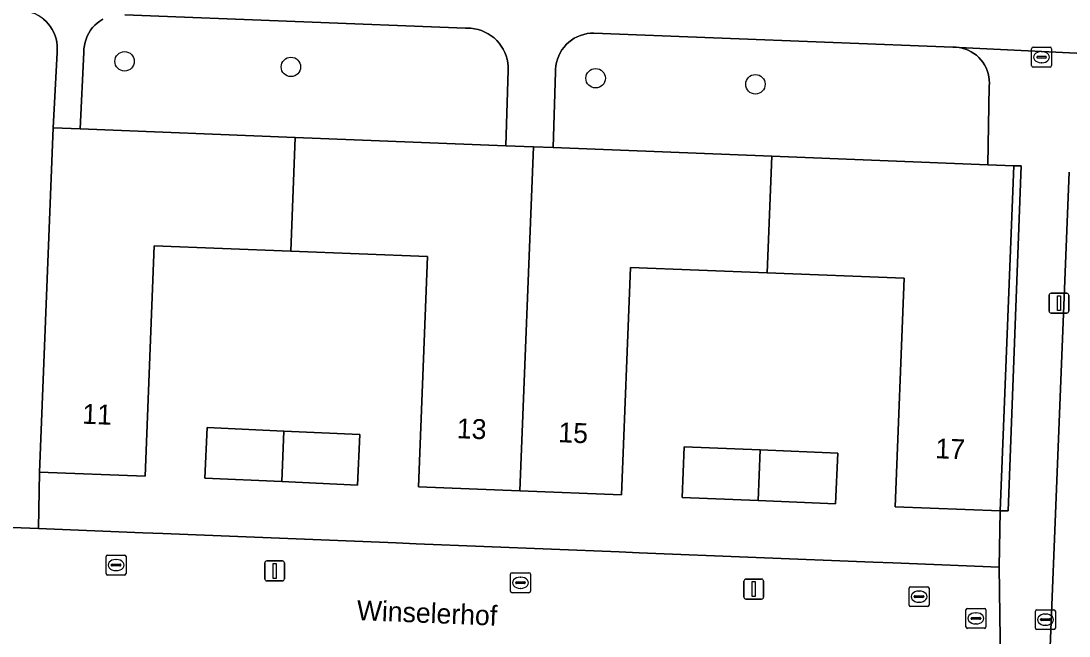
# Model space of a CAD drawing. Extents: x 160786 to 161429, y 386828 to 387485.
# Drawn here: x 161039.4 to 161092.1, y 387016.5 to 387047.4 of the extents above; entities that cross this region are included whole.
import ezdxf

# ---------------------------------------------------------------- set-up
doc = ezdxf.new("R2010")
doc.units = 0
for name, color, linetype in [('IMGEO_Boom', 7, 'Continuous'), ('IMGEO_Brandkraan', 7, 'Continuous'), ('IMGEO_Erf', 7, 'Continuous'), ('IMGEO_Grasland_overig', 7, 'Continuous'), ('IMGEO_Groenvoorziening', 7, 'Continuous'), ('IMGEO_Kolk', 7, 'Continuous'), ('IMGEO_Lichtmast', 7, 'Continuous'), ('IMGEO_Openbare_ruimte_label', 7, 'Continuous'), ('IMGEO_Pand', 7, 'Continuous'), ('IMGEO_Pand_nummerreeks', 7, 'Continuous'), ('IMGEO_Rioolput', 7, 'Continuous'), ('IMGEO_Voetpad_open', 7, 'Continuous')]:
    doc.layers.add(name, color=color, linetype=linetype)

msp = doc.modelspace()

# ---------------------------------------------------------------- linework, layer by layer
at = {"layer": 'IMGEO_Boom'}
for centre in [(161044.621, 387045.348), (161052.986, 387045.068), (161068.308, 387044.499), (161076.343, 387044.195)]:
    msp.add_circle(centre, 0.489, dxfattribs=at)
at = {"layer": 'IMGEO_Brandkraan'}
for p, q in [((161090.233, 387045.132), (161090.233, 387045.984)), ((161090.308, 387046.058), (161091.16, 387046.058)), ((161090.492, 387045.552), (161090.492, 387045.564)), ((161090.535, 387045.601), (161090.933, 387045.601)), ((161090.721, 387045.838), (161090.746, 387045.838)), ((161090.976, 387045.564), (161090.976, 387045.552)), ((161091.234, 387045.984), (161091.234, 387045.132)), ((161091.16, 387045.058), (161090.308, 387045.058)), ((161090.93, 387045.515), (161090.532, 387045.515)), ((161090.744, 387045.278), (161090.719, 387045.278))]:
    msp.add_line(p, q, dxfattribs=at)
for points in [[(161090.233, 387045.132), (161090.233, 387045.984)], [(161090.308, 387046.058), (161091.16, 387046.058)], [(161091.234, 387045.984), (161091.234, 387045.132)], [(161091.16, 387045.058), (161090.308, 387045.058)]]:
    msp.add_lwpolyline(points, dxfattribs=at)
for centre, radius, start, end in [((161090.31, 387045.982), 0.0765, 91.552, 178.448), ((161090.31, 387045.982), 0.0765, 91.552, 178.448), ((161090.532, 387045.561), 0.0403, 85.8775, 175.7526), ((161090.529, 387045.551), 0.0366, 178.938, 274.7102), ((161090.933, 387045.558), 0.043, 264.8664, 352.4533), ((161090.937, 387045.563), 0.0386, 1.7309, 96.639), ((161091.158, 387045.982), 0.0765, 1.552, 88.448), ((161091.158, 387045.982), 0.0765, 1.552, 88.448), ((161090.31, 387045.134), 0.0765, 181.552, 268.448), ((161090.31, 387045.134), 0.0765, 181.552, 268.448), ((161091.158, 387045.134), 0.0765, 271.552, 358.448), ((161091.158, 387045.134), 0.0765, 271.552, 358.448)]:
    msp.add_arc(centre, radius, start, end, dxfattribs=at)
for centre, major_axis, ratio, start_param, end_param in [((161090.72, 387045.558), (-0.387, 0.002), 0.722429, 4.712389, 7.853982), ((161090.745, 387045.558), (-0.39, 0.002), 0.717154, 1.570796, 4.712389)]:
    msp.add_ellipse(centre, major_axis=major_axis, ratio=ratio, start_param=start_param, end_param=end_param, dxfattribs=at)
at = {"layer": 'IMGEO_Erf'}
msp.add_lwpolyline([(161092.128, 387039.776), (161090.524, 387000), (161090.045, 386988.116), (161088.04, 386938.415)], dxfattribs=at)
for points in [[(161088.653, 387022.747), (161083.368, 387022.956), (161083.821, 387034.446), (161076.938, 387034.717), (161070.057, 387034.988), (161069.606, 387023.557), (161064.5, 387023.758), (161059.398, 387023.959), (161059.855, 387035.539), (161052.982, 387035.81), (161046.111, 387036.081), (161045.654, 387024.488), (161040.347, 387024.697), (161040.297, 387021.856), (161045.542, 387021.645), (161046.541, 387021.605), (161058.286, 387021.134), (161059.285, 387021.094), (161069.492, 387020.685), (161070.491, 387020.645), (161082.258, 387020.173), (161083.257, 387020.133), (161088.605, 387019.918)], [(161056.335, 387024.044), (161052.525, 387024.218), (161048.651, 387024.394), (161048.767, 387026.938), (161052.626, 387026.762), (161056.451, 387026.588)], [(161076.487, 387023.268), (161072.653, 387023.428), (161072.759, 387025.972), (161076.587, 387025.812), (161080.481, 387025.65), (161080.375, 387023.106)]]:
    msp.add_lwpolyline(points, close=True, dxfattribs=at)
at = {"layer": 'IMGEO_Grasland_overig'}
msp.add_lwpolyline([(161088.036, 387040.148), (161088.101, 387044.096), (161088.11, 387044.255), (161088.104, 387044.415), (161088.085, 387044.573), (161088.051, 387044.729), (161088.003, 387044.882), (161087.942, 387045.029), (161087.869, 387045.171), (161087.782, 387045.305), (161087.684, 387045.431), (161087.576, 387045.548), (161087.457, 387045.655), (161087.329, 387045.75), (161087.193, 387045.834), (161087.05, 387045.906), (161086.902, 387045.964), (161086.748, 387046.009), (161086.592, 387046.04), (161086.433, 387046.056), (161086.278, 387046.059), (161068.217, 387046.773), (161068.046, 387046.766), (161067.875, 387046.743), (161067.708, 387046.706), (161067.545, 387046.653), (161067.387, 387046.586), (161067.235, 387046.506), (161067.091, 387046.412), (161066.957, 387046.306), (161066.832, 387046.188), (161066.718, 387046.059), (161066.617, 387045.921), (161066.528, 387045.774), (161066.452, 387045.62), (161066.391, 387045.46), (161066.344, 387045.295), (161066.312, 387045.126), (161066.295, 387044.955), (161066.293, 387044.826), (161066.166, 387041.01), (161077.169, 387040.577)], close=True, dxfattribs=at)
at = {"layer": 'IMGEO_Groenvoorziening'}
for points in [[(161035.04, 387022.067), (161040.297, 387021.856), (161040.347, 387024.697), (161041.029, 387042.001), (161041.225, 387045.801), (161041.235, 387045.97), (161041.23, 387046.14), (161041.21, 387046.309), (161041.175, 387046.475), (161041.126, 387046.637), (161041.062, 387046.794), (161040.984, 387046.945), (161040.893, 387047.088), (161040.789, 387047.223), (161040.674, 387047.348), (161040.549, 387047.462), (161040.413, 387047.564), (161040.269, 387047.654), (161040.118, 387047.731), (161039.96, 387047.793), (161039.797, 387047.842), (161039.631, 387047.876), (161039.462, 387047.894), (161039.293, 387047.898)], [(161043.519, 387047.463), (161043.378, 387047.375), (161043.245, 387047.275), (161043.123, 387047.164), (161043.01, 387047.042), (161042.909, 387046.91), (161042.82, 387046.77), (161042.744, 387046.622), (161042.681, 387046.469), (161042.633, 387046.31), (161042.598, 387046.148), (161042.579, 387045.983), (161042.574, 387045.815), (161042.387, 387041.947), (161053.207, 387041.521), (161063.786, 387041.104), (161063.914, 387044.91), (161063.912, 387045.093), (161063.893, 387045.274), (161063.858, 387045.453), (161063.808, 387045.629), (161063.742, 387045.799), (161063.661, 387045.963), (161063.565, 387046.118), (161063.456, 387046.265), (161063.335, 387046.401), (161063.202, 387046.526), (161063.058, 387046.638), (161062.905, 387046.738), (161062.743, 387046.823), (161062.575, 387046.893), (161062.4, 387046.948), (161062.222, 387046.987), (161062.041, 387047.01), (161061.859, 387047.017), (161061.76, 387047.014), (161044.639, 387047.69)]]:
    msp.add_lwpolyline(points, dxfattribs=at)
msp.add_lwpolyline([(161088.653, 387022.747), (161089.055, 387022.743), (161089.703, 387040.094), (161089.337, 387040.097)], close=True, dxfattribs=at)
at = {"layer": 'IMGEO_Kolk'}
for p, q in [((161043.693, 387019.597), (161043.693, 387020.449)), ((161043.768, 387020.523), (161044.62, 387020.523)), ((161044.181, 387020.303), (161044.206, 387020.303)), ((161044.694, 387020.449), (161044.694, 387019.597)), ((161043.952, 387020.017), (161043.952, 387020.029)), ((161044.39, 387019.98), (161043.992, 387019.98)), ((161043.995, 387020.066), (161044.393, 387020.066)), ((161044.204, 387019.743), (161044.179, 387019.743)), ((161044.436, 387020.029), (161044.436, 387020.017)), ((161044.62, 387019.523), (161043.768, 387019.523)), ((161064.029, 387018.708), (161064.029, 387019.56)), ((161064.104, 387019.634), (161064.956, 387019.634)), ((161064.517, 387019.414), (161064.542, 387019.414)), ((161065.03, 387019.56), (161065.03, 387018.708)), ((161064.288, 387019.128), (161064.288, 387019.14)), ((161064.726, 387019.091), (161064.328, 387019.091)), ((161064.331, 387019.177), (161064.729, 387019.177)), ((161064.54, 387018.854), (161064.515, 387018.854)), ((161064.772, 387019.14), (161064.772, 387019.128)), ((161084.072, 387018.01), (161084.072, 387018.862)), ((161084.147, 387018.936), (161084.999, 387018.936)), ((161084.56, 387018.716), (161084.585, 387018.716)), ((161085.073, 387018.862), (161085.073, 387018.01)), ((161064.956, 387018.634), (161064.104, 387018.634)), ((161084.331, 387018.43), (161084.331, 387018.442)), ((161084.769, 387018.393), (161084.371, 387018.393)), ((161084.374, 387018.479), (161084.772, 387018.479)), ((161084.583, 387018.156), (161084.558, 387018.156)), ((161084.815, 387018.442), (161084.815, 387018.43)), ((161084.999, 387017.936), (161084.147, 387017.936))]:
    msp.add_line(p, q, dxfattribs=at)
for points in [[(161043.693, 387019.597), (161043.693, 387020.449)], [(161043.768, 387020.523), (161044.62, 387020.523)], [(161044.694, 387020.449), (161044.694, 387019.597)], [(161044.62, 387019.523), (161043.768, 387019.523)], [(161064.029, 387018.708), (161064.029, 387019.56)], [(161064.104, 387019.634), (161064.956, 387019.634)], [(161065.03, 387019.56), (161065.03, 387018.708)], [(161084.072, 387018.01), (161084.072, 387018.862)], [(161084.147, 387018.936), (161084.999, 387018.936)], [(161085.073, 387018.862), (161085.073, 387018.01)], [(161064.956, 387018.634), (161064.104, 387018.634)], [(161084.999, 387017.936), (161084.147, 387017.936)]]:
    msp.add_lwpolyline(points, dxfattribs=at)
for centre, radius, start, end in [((161043.77, 387020.447), 0.0765, 91.552, 178.448), ((161043.77, 387020.447), 0.0765, 91.552, 178.448), ((161044.618, 387020.447), 0.0765, 1.552, 88.448), ((161044.618, 387020.447), 0.0765, 1.552, 88.448), ((161043.992, 387020.026), 0.0403, 85.8775, 175.7526), ((161043.989, 387020.016), 0.0366, 178.938, 274.7102), ((161044.393, 387020.023), 0.043, 264.8664, 352.4533), ((161044.397, 387020.028), 0.0386, 1.7309, 96.639), ((161043.77, 387019.599), 0.0765, 181.552, 268.448), ((161043.77, 387019.599), 0.0765, 181.552, 268.448), ((161044.618, 387019.599), 0.0765, 271.552, 358.448), ((161044.618, 387019.599), 0.0765, 271.552, 358.448), ((161064.106, 387019.558), 0.0765, 91.552, 178.448), ((161064.106, 387019.558), 0.0765, 91.552, 178.448), ((161064.954, 387019.558), 0.0765, 1.552, 88.448), ((161064.954, 387019.558), 0.0765, 1.552, 88.448), ((161064.106, 387018.71), 0.0765, 181.552, 268.448), ((161064.106, 387018.71), 0.0765, 181.552, 268.448), ((161064.328, 387019.137), 0.0403, 85.8775, 175.7526), ((161064.325, 387019.127), 0.0366, 178.938, 274.7102), ((161064.729, 387019.134), 0.043, 264.8664, 352.4533), ((161064.733, 387019.139), 0.0386, 1.7309, 96.639), ((161064.954, 387018.71), 0.0765, 271.552, 358.448), ((161064.954, 387018.71), 0.0765, 271.552, 358.448), ((161084.149, 387018.86), 0.0765, 91.552, 178.448), ((161084.149, 387018.86), 0.0765, 91.552, 178.448), ((161084.997, 387018.86), 0.0765, 1.552, 88.448), ((161084.997, 387018.86), 0.0765, 1.552, 88.448), ((161084.371, 387018.439), 0.0403, 85.8775, 175.7526), ((161084.368, 387018.429), 0.0366, 178.938, 274.7102), ((161084.772, 387018.436), 0.043, 264.8664, 352.4533), ((161084.776, 387018.441), 0.0386, 1.7309, 96.639), ((161084.149, 387018.012), 0.0765, 181.552, 268.448), ((161084.149, 387018.012), 0.0765, 181.552, 268.448), ((161084.997, 387018.012), 0.0765, 271.552, 358.448), ((161084.997, 387018.012), 0.0765, 271.552, 358.448)]:
    msp.add_arc(centre, radius, start, end, dxfattribs=at)
for centre, major_axis, ratio, start_param, end_param in [((161044.18, 387020.023), (-0.387, 0.002), 0.722429, 4.712389, 7.853982), ((161044.205, 387020.023), (-0.39, 0.002), 0.717154, 1.570796, 4.712389), ((161064.516, 387019.134), (-0.387, 0.002), 0.722429, 4.712389, 7.853982), ((161064.541, 387019.134), (-0.39, 0.002), 0.717154, 1.570796, 4.712389), ((161084.559, 387018.436), (-0.387, 0.002), 0.722429, 4.712389, 7.853982), ((161084.584, 387018.436), (-0.39, 0.002), 0.717154, 1.570796, 4.712389)]:
    msp.add_ellipse(centre, major_axis=major_axis, ratio=ratio, start_param=start_param, end_param=end_param, dxfattribs=at)
at = {"layer": 'IMGEO_Lichtmast'}
for p, q in [((161091.111, 387032.791), (161091.111, 387033.591)), ((161091.111, 387033.591), (161091.111, 387032.791)), ((161091.211, 387033.691), (161092.001, 387033.691)), ((161092.001, 387033.691), (161091.211, 387033.691)), ((161092.101, 387033.591), (161092.101, 387032.791)), ((161092.101, 387032.791), (161092.101, 387033.591)), ((161092.001, 387032.691), (161091.211, 387032.691)), ((161091.211, 387032.691), (161092.001, 387032.691)), ((161051.671, 387019.331), (161051.671, 387020.131)), ((161051.671, 387020.131), (161051.671, 387019.331)), ((161051.771, 387020.231), (161052.561, 387020.231)), ((161052.561, 387020.231), (161051.771, 387020.231)), ((161052.661, 387020.131), (161052.661, 387019.331)), ((161052.661, 387019.331), (161052.661, 387020.131)), ((161052.561, 387019.231), (161051.771, 387019.231)), ((161051.771, 387019.231), (161052.561, 387019.231)), ((161075.764, 387018.418), (161075.764, 387019.218)), ((161075.764, 387019.218), (161075.764, 387018.418)), ((161075.864, 387019.318), (161076.654, 387019.318)), ((161076.654, 387019.318), (161075.864, 387019.318)), ((161076.754, 387019.218), (161076.754, 387018.418)), ((161076.754, 387018.418), (161076.754, 387019.218)), ((161076.654, 387018.318), (161075.864, 387018.318)), ((161075.864, 387018.318), (161076.654, 387018.318))]:
    msp.add_line(p, q, dxfattribs=at)
for points in [[(161091.531, 387033.566), (161091.681, 387033.566), (161091.681, 387032.816), (161091.531, 387032.816), (161091.531, 387033.566)], [(161052.091, 387020.106), (161052.241, 387020.106), (161052.241, 387019.356), (161052.091, 387019.356), (161052.091, 387020.106)], [(161076.184, 387019.193), (161076.334, 387019.193), (161076.334, 387018.443), (161076.184, 387018.443), (161076.184, 387019.193)]]:
    msp.add_lwpolyline(points, dxfattribs=at)
for centre, start, end in [((161091.211, 387033.591), 90, 180), ((161091.211, 387033.591), 90, 180), ((161092.001, 387033.591), 0, 90), ((161092.001, 387033.591), 360, 90), ((161091.211, 387032.791), 180, 270), ((161091.211, 387032.791), 180, 270), ((161092.001, 387032.791), 270, 0), ((161092.001, 387032.791), 270, 0), ((161051.771, 387020.131), 90, 180), ((161051.771, 387020.131), 90, 180), ((161052.561, 387020.131), 0, 90), ((161052.561, 387020.131), 360, 90), ((161051.771, 387019.331), 180, 270), ((161051.771, 387019.331), 180, 270), ((161052.561, 387019.331), 270, 0), ((161052.561, 387019.331), 270, 0), ((161075.864, 387019.218), 90, 180), ((161075.864, 387019.218), 90, 180), ((161076.654, 387019.218), 0, 90), ((161076.654, 387019.218), 360, 90), ((161075.864, 387018.418), 180, 270), ((161075.864, 387018.418), 180, 270), ((161076.654, 387018.418), 270, 0), ((161076.654, 387018.418), 270, 0)]:
    msp.add_arc(centre, 0.1, start, end, dxfattribs=at)
at = {"layer": 'IMGEO_Pand'}
for points in [[(161042.387, 387041.947), (161041.029, 387042.001), (161040.347, 387024.697), (161045.654, 387024.488), (161046.111, 387036.081), (161052.982, 387035.81), (161053.207, 387041.521)], [(161063.786, 387041.104), (161053.207, 387041.521), (161052.982, 387035.81), (161059.855, 387035.539), (161059.398, 387023.959), (161064.5, 387023.758), (161065.182, 387041.049)], [(161066.166, 387041.01), (161065.182, 387041.049), (161064.5, 387023.758), (161069.606, 387023.557), (161070.057, 387034.988), (161076.938, 387034.717), (161077.169, 387040.577)], [(161077.169, 387040.577), (161076.938, 387034.717), (161083.821, 387034.446), (161083.368, 387022.956), (161088.653, 387022.747), (161089.337, 387040.097), (161088.036, 387040.148)], [(161052.626, 387026.762), (161048.767, 387026.938), (161048.651, 387024.394), (161052.525, 387024.218)], [(161052.525, 387024.218), (161056.335, 387024.044), (161056.451, 387026.588), (161052.626, 387026.762)], [(161076.587, 387025.812), (161072.759, 387025.972), (161072.653, 387023.428), (161076.487, 387023.268)], [(161076.487, 387023.268), (161080.375, 387023.106), (161080.481, 387025.65), (161076.587, 387025.812)]]:
    msp.add_lwpolyline(points, close=True, dxfattribs=at)
at = {"layer": 'IMGEO_Rioolput'}
for p, q in [((161086.929, 387016.918), (161086.929, 387017.77)), ((161087.004, 387017.844), (161087.856, 387017.844)), ((161087.417, 387017.624), (161087.442, 387017.624)), ((161087.93, 387017.77), (161087.93, 387016.918)), ((161090.426, 387016.854), (161090.426, 387017.706)), ((161090.501, 387017.78), (161091.353, 387017.78)), ((161091.427, 387017.706), (161091.427, 387016.854)), ((161087.188, 387017.338), (161087.188, 387017.35)), ((161087.626, 387017.301), (161087.228, 387017.301)), ((161087.231, 387017.387), (161087.629, 387017.387)), ((161087.672, 387017.35), (161087.672, 387017.338)), ((161090.685, 387017.274), (161090.685, 387017.286)), ((161091.123, 387017.237), (161090.725, 387017.237)), ((161090.728, 387017.323), (161091.126, 387017.323)), ((161090.914, 387017.56), (161090.939, 387017.56)), ((161091.169, 387017.286), (161091.169, 387017.274)), ((161087.856, 387016.844), (161087.004, 387016.844)), ((161087.44, 387017.064), (161087.415, 387017.064)), ((161091.353, 387016.78), (161090.501, 387016.78)), ((161090.937, 387017), (161090.912, 387017))]:
    msp.add_line(p, q, dxfattribs=at)
for points in [[(161086.929, 387016.918), (161086.929, 387017.77)], [(161087.004, 387017.844), (161087.856, 387017.844)], [(161087.93, 387017.77), (161087.93, 387016.918)], [(161090.426, 387016.854), (161090.426, 387017.706)], [(161090.501, 387017.78), (161091.353, 387017.78)], [(161091.427, 387017.706), (161091.427, 387016.854)], [(161087.856, 387016.844), (161087.004, 387016.844)], [(161091.353, 387016.78), (161090.501, 387016.78)]]:
    msp.add_lwpolyline(points, dxfattribs=at)
for centre, radius, start, end in [((161087.006, 387017.768), 0.0765, 91.552, 178.448), ((161087.006, 387017.768), 0.0765, 91.552, 178.448), ((161087.854, 387017.768), 0.0765, 1.552, 88.448), ((161087.854, 387017.768), 0.0765, 1.552, 88.448), ((161090.503, 387017.704), 0.0765, 91.552, 178.448), ((161090.503, 387017.704), 0.0765, 91.552, 178.448), ((161091.351, 387017.704), 0.0765, 1.552, 88.448), ((161091.351, 387017.704), 0.0765, 1.552, 88.448), ((161087.228, 387017.347), 0.0403, 85.8775, 175.7526), ((161087.225, 387017.337), 0.0366, 178.938, 274.7102), ((161087.629, 387017.344), 0.043, 264.8664, 352.4533), ((161087.633, 387017.349), 0.0386, 1.7309, 96.639), ((161090.725, 387017.283), 0.0403, 85.8775, 175.7526), ((161090.722, 387017.273), 0.0366, 178.938, 274.7102), ((161091.126, 387017.28), 0.043, 264.8664, 352.4533), ((161091.13, 387017.285), 0.0386, 1.7309, 96.639), ((161087.006, 387016.92), 0.0765, 181.552, 268.448), ((161087.006, 387016.92), 0.0765, 181.552, 268.448), ((161087.854, 387016.92), 0.0765, 271.552, 358.448), ((161087.854, 387016.92), 0.0765, 271.552, 358.448), ((161090.503, 387016.856), 0.0765, 181.552, 268.448), ((161090.503, 387016.856), 0.0765, 181.552, 268.448), ((161091.351, 387016.856), 0.0765, 271.552, 358.448), ((161091.351, 387016.856), 0.0765, 271.552, 358.448)]:
    msp.add_arc(centre, radius, start, end, dxfattribs=at)
for centre, major_axis, ratio, start_param, end_param in [((161087.416, 387017.344), (-0.387, 0.002), 0.722429, 4.712389, 7.853982), ((161087.441, 387017.344), (-0.39, 0.002), 0.717154, 1.570796, 4.712389), ((161090.913, 387017.28), (-0.387, 0.002), 0.722429, 4.712389, 7.853982), ((161090.938, 387017.28), (-0.39, 0.002), 0.717154, 1.570796, 4.712389)]:
    msp.add_ellipse(centre, major_axis=major_axis, ratio=ratio, start_param=start_param, end_param=end_param, dxfattribs=at)
at = {"layer": 'IMGEO_Voetpad_open'}
for points in [[(161044.639, 387047.69), (161061.76, 387047.014), (161061.859, 387047.017), (161062.041, 387047.01), (161062.222, 387046.987), (161062.4, 387046.948), (161062.575, 387046.893), (161062.743, 387046.823), (161062.905, 387046.738), (161063.058, 387046.638), (161063.202, 387046.526), (161063.335, 387046.401), (161063.456, 387046.265), (161063.565, 387046.118), (161063.661, 387045.963), (161063.742, 387045.799), (161063.808, 387045.629), (161063.858, 387045.453), (161063.893, 387045.274), (161063.912, 387045.093), (161063.914, 387044.91), (161063.786, 387041.104), (161065.182, 387041.049), (161066.166, 387041.01), (161066.293, 387044.826), (161066.295, 387044.955), (161066.312, 387045.126), (161066.344, 387045.295), (161066.391, 387045.46), (161066.452, 387045.62), (161066.528, 387045.774), (161066.617, 387045.921), (161066.718, 387046.059), (161066.832, 387046.188), (161066.957, 387046.306), (161067.091, 387046.412), (161067.235, 387046.506), (161067.387, 387046.586), (161067.545, 387046.653), (161067.708, 387046.706), (161067.875, 387046.743), (161068.046, 387046.766), (161068.217, 387046.773), (161086.278, 387046.059), (161086.433, 387046.056), (161086.592, 387046.04), (161094.218, 387045.676)], [(161040.549, 387047.462), (161040.674, 387047.348), (161040.789, 387047.223), (161040.893, 387047.088), (161040.984, 387046.945), (161041.062, 387046.794), (161041.126, 387046.637), (161041.175, 387046.475), (161041.21, 387046.309), (161041.23, 387046.14), (161041.235, 387045.97), (161041.225, 387045.801), (161041.029, 387042.001), (161042.387, 387041.947), (161042.574, 387045.815), (161042.579, 387045.983), (161042.598, 387046.148), (161042.633, 387046.31), (161042.681, 387046.469), (161042.744, 387046.622), (161042.82, 387046.77), (161042.909, 387046.91), (161043.01, 387047.042), (161043.123, 387047.164), (161043.245, 387047.275), (161043.378, 387047.375), (161043.519, 387047.463)], [(161094.218, 387045.676), (161086.592, 387046.04), (161086.748, 387046.009), (161086.902, 387045.964), (161087.05, 387045.906), (161087.193, 387045.834), (161087.329, 387045.75), (161087.457, 387045.655), (161087.576, 387045.548), (161087.684, 387045.431), (161087.782, 387045.305), (161087.869, 387045.171), (161087.942, 387045.029), (161088.003, 387044.882), (161088.051, 387044.729), (161088.085, 387044.573), (161088.104, 387044.415), (161088.11, 387044.255), (161088.101, 387044.096), (161088.036, 387040.148), (161089.337, 387040.097), (161089.703, 387040.094), (161089.055, 387022.743), (161088.653, 387022.747), (161088.605, 387019.918), (161088.679, 387013.929)], [(161090.524, 387000), (161092.128, 387039.776)]]:
    msp.add_lwpolyline(points, dxfattribs=at)
msp.add_lwpolyline([(161088.605, 387019.918), (161083.257, 387020.133), (161082.258, 387020.173), (161070.491, 387020.645), (161069.492, 387020.685), (161059.285, 387021.094), (161058.286, 387021.134), (161046.541, 387021.605), (161045.542, 387021.645), (161040.297, 387021.856), (161035.04, 387022.067), (161031.043, 387022.227), (161030.488, 387022.25), (161030.281, 387016.134), (161030.788, 387016.117), (161040.103, 387015.882), (161052.204, 387015.396), (161064.155, 387014.915), (161076.105, 387014.435), (161088.206, 387013.949), (161088.679, 387013.929)], close=True, dxfattribs=at)

# ---------------------------------------------------------------- texts
at = {"layer": 'IMGEO_Openbare_ruimte_label'}
msp.add_text('Winselerhof', height=1, rotation=357.7071, dxfattribs=at).set_placement((161056.283, 387017.259))
at = {"layer": 'IMGEO_Pand_nummerreeks'}
for s, rotation, p in [('11', 357.7447, (161042.479, 387027.134)), ('13', 357.7448, (161061.315, 387026.405)), ('15', 357.7448, (161066.419, 387026.204)), ('17', 357.7354, (161085.376, 387025.398))]:
    msp.add_text(s, height=1, rotation=rotation, dxfattribs=at).set_placement(p)

doc.saveas('drawing.dxf')
